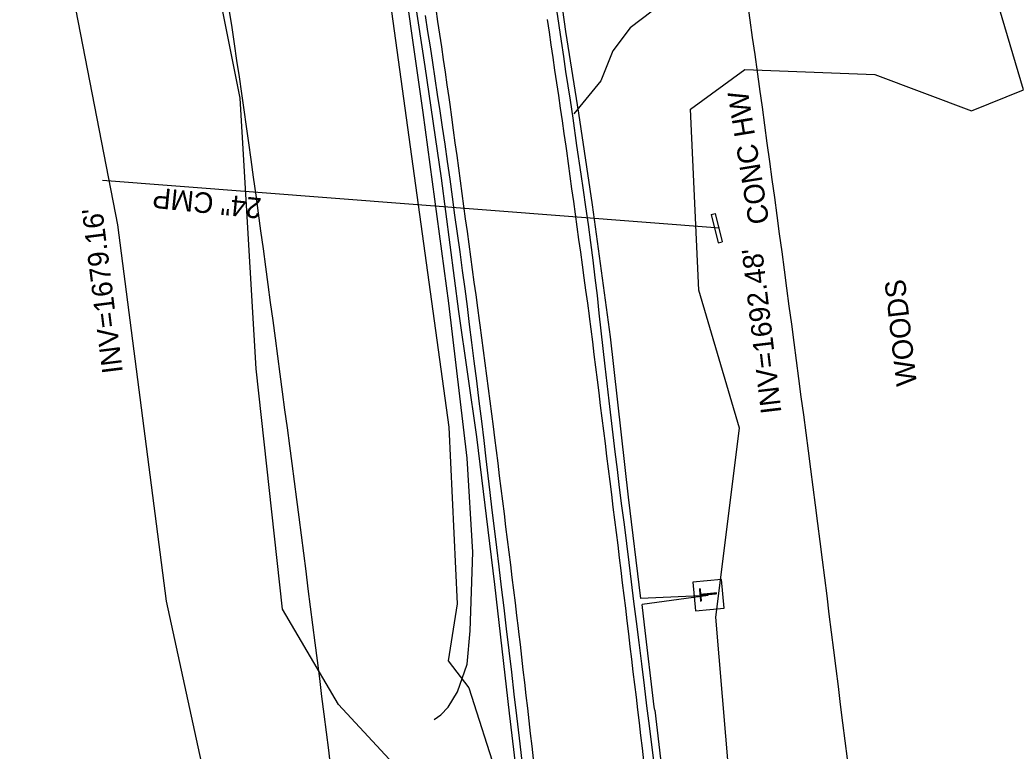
# Model space of a CAD drawing. Extents: x 472260 to 482161, y 489063 to 507124.
# Drawn here: x 477899.5 to 478093.4, y 498501.7 to 498644 of the extents above; entities that cross this region are included whole.
import ezdxf

# ---------------------------------------------------------------- set-up
doc = ezdxf.new("R2010")
doc.units = 0
for name, color, linetype in [('Exist Structure Minor Drop Inlet Cogo Elevation', 7, 'Continuous'), ('Exist Structure Minor Pipes CMP 30 Inch', 7, 'Continuous'), ('Exist Structure Minor Pipes HDPE 18 Inch', 7, 'Continuous'), ('Prop Drainage Structure Catch Basin Convert From Junction Box Label', 7, 'Continuous'), ('Prop Drainage Structure Drop Inlet Grate 2 Narrow Slots and Sag Grates 840 24 CELL', 7, 'Continuous'), ('Prop Drainage Structure Headwall CELL', 7, 'Continuous'), ('Prop Drainage Structure Pipe RCP 18in Class III', 7, 'Continuous'), ('Prop Drainage Structure Pipe RCP 66in Class III', 7, 'Continuous'), ('Prop Drainage Structure Pipe Stub Out CELL', 7, 'Continuous'), ('Prop Drainage Structure Plot Symbol 50 Scale', 7, 'Continuous'), ('Prop Drainage Structure Plot Symbol 50 Scale CELL', 7, 'Continuous'), ('Prop Drainage Structure Tops and Inverts LABEL', 7, 'Continuous'), ('Prop Earthen Structure Head Ditch', 7, 'Continuous'), ('Prop Erosion Rip Rap Class B', 7, 'Continuous'), ('Prop Erosion Rip Rap Pad at Outlet Label', 7, 'Continuous')]:
    doc.layers.add(name, color=color, linetype=linetype)

msp = doc.modelspace()

# ---------------------------------------------------------------- linework, layer by layer
at = {"layer": 'Exist Structure Minor Drop Inlet Cogo Elevation'}
for centre, radius, start, end in [((475642.7, 498298.63), 2423.66, 7.87106, 10.42705), ((475642.7, 498298.63), 2323.66, 7.87106, 10.42705), ((469239.4, 497413.39), 8887.86, 6.405023, 7.871057), ((469239.4, 497413.39), 8787.86, 6.405023, 7.871057)]:
    msp.add_arc(centre, radius, start, end, dxfattribs=at)
at = {"layer": 'Prop Drainage Structure Catch Basin Convert From Junction Box Label'}
for p, q in [((478033.49, 498531.98), (478020.37, 498531.37)), ((478033.49, 498531.98), (478020.58, 498530.25)), ((478023.05, 498509.69), (478022.98, 498510.29))]:
    msp.add_line(p, q, dxfattribs=at)
for points in [[(478020.37, 498531.37), (478017.95, 498551.09), (478014.43, 498582.34), (478010.97, 498607.98), (478008.3, 498625.86), (478005.77, 498641.71), (478003, 498661.43), (477999.51, 498683.4), (477996.51, 498701.33)], [(478002.63, 498442.95), (478002.08, 498447.9), (477997.91, 498482.93), (477994.76, 498509.09), (477991.94, 498534.13), (477988.4, 498562.87), (477984.93, 498587.23), (477981.55, 498613.17), (477978.36, 498634.94), (477973.78, 498665.15), (477969.61, 498690.6), (477968.51, 498697.7)], [(478022.98, 498510.29), (478021.09, 498526.24), (478020.58, 498530.25)], [(478023.05, 498509.69), (478024.96, 498493.54), (478028.85, 498462.94), (478029.49, 498456.54)]]:
    msp.add_lwpolyline(points, dxfattribs=at)
at = {"layer": 'Prop Drainage Structure Drop Inlet Grate 2 Narrow Slots and Sag Grates 840 24 CELL'}
for points in [[(477999.46, 498500.17), (477999.17, 498502.65), (477998.89, 498505.13), (477998.61, 498507.6), (477998.32, 498510.08), (477998.04, 498512.55), (477997.75, 498515.03), (477997.47, 498517.5), (477997.19, 498519.98), (477996.9, 498522.46), (477996.62, 498524.93), (477996.54, 498525.6), (477996.24, 498528.07), (477995.93, 498530.54), (477995.62, 498533.01), (477995.32, 498535.49), (477995.01, 498537.96), (477994.7, 498540.43), (477994.39, 498542.9), (477994.09, 498545.37), (477993.78, 498547.85), (477993.47, 498550.32), (477993.17, 498552.79), (477992.86, 498555.26), (477992.55, 498557.73), (477992.25, 498560.21), (477991.94, 498562.68), (477991.67, 498564.85), (477991.34, 498567.32), (477991.01, 498569.79), (477990.69, 498572.26), (477990.36, 498574.73), (477990.03, 498577.2), (477989.7, 498579.66), (477989.37, 498582.13), (477989.05, 498584.6), (477988.93, 498585.51), (477988.59, 498587.98), (477988.26, 498590.45), (477987.92, 498592.92), (477987.59, 498595.39), (477987.25, 498597.86), (477986.91, 498600.33), (477986.58, 498602.8), (477986.24, 498605.26), (477985.91, 498607.73), (477985.57, 498610.2), (477985.24, 498612.67), (477984.9, 498615.14), (477984.57, 498617.61), (477984.23, 498620.08), (477983.9, 498622.55), (477983.56, 498625.02), (477983.23, 498627.49), (477983.04, 498628.89), (477982.67, 498631.35), (477982.31, 498633.82), (477981.94, 498636.29), (477981.58, 498638.75), (477981.21, 498641.22), (477980.85, 498643.69), (477980.48, 498646.15)], [(478020.96, 498499.8), (478020.67, 498502.28), (478020.37, 498504.75), (478020.07, 498507.22), (478019.78, 498509.7), (478019.48, 498512.17), (478019.18, 498514.65), (478018.89, 498517.12), (478018.59, 498519.6), (478018.29, 498522.07), (478018, 498524.55), (478017.7, 498527.02), (478017.4, 498529.5), (478017.11, 498531.97), (478016.81, 498534.44), (478016.53, 498536.82), (478016.22, 498539.29), (478015.91, 498541.76), (478015.6, 498544.23), (478015.29, 498546.71), (478014.99, 498549.18), (478014.68, 498551.65), (478014.37, 498554.13), (478014.06, 498556.6), (478013.75, 498559.07), (478013.45, 498561.54), (478013.14, 498564.02), (478012.83, 498566.49), (478012.52, 498568.96), (478012.22, 498571.43), (478011.91, 498573.91), (478011.6, 498576.38), (478011.29, 498578.85), (478010.98, 498581.33), (478010.68, 498583.8), (478010.37, 498586.27), (478010.35, 498586.42), (478010.01, 498588.89), (478009.67, 498591.36), (478009.33, 498593.82), (478008.99, 498596.29), (478008.65, 498598.76), (478008.31, 498601.23), (478007.97, 498603.7), (478007.63, 498606.17), (478007.29, 498608.64), (478006.95, 498611.11), (478006.61, 498613.58), (478006.27, 498616.05), (478005.93, 498618.52), (478005.81, 498619.39), (478005.45, 498621.85), (478005.09, 498624.32), (478004.72, 498626.79), (478004.36, 498629.25), (478004, 498631.72), (478003.63, 498634.19), (478003.27, 498636.65), (478002.91, 498639.12), (478002.54, 498641.58), (478002.18, 498644.05)]]:
    msp.add_lwpolyline(points, dxfattribs=at)
at = {"layer": 'Prop Drainage Structure Headwall CELL'}
msp.add_line((477915.57, 498612.76), (478035.68, 498603.54), dxfattribs=at)
at = {"layer": 'Prop Drainage Structure Pipe RCP 18in Class III'}
msp.add_lwpolyline([(478067.38, 498733.66), (478056.64, 498702.95), (478045.19, 498672.47), (478038.91, 498659.85), (478033.38, 498654.47), (478024.69, 498647.29), (478018.26, 498642.42), (478014.87, 498637.95), (478012.54, 498632.09), (478007.31, 498625.71)], dxfattribs=at)
at = {"layer": 'Prop Drainage Structure Pipe Stub Out CELL'}
for points in [[(478022.93, 498499.35), (478022.49, 498502.95), (478022.03, 498506.64), (478021.55, 498510.48), (478021.05, 498514.49), (478020.53, 498518.65), (478020, 498522.83), (478019.5, 498526.89), (478019.01, 498530.83), (478018.55, 498534.64), (478018.09, 498538.38), (478017.62, 498542.09), (478017.16, 498545.77), (478016.68, 498549.42), (478016.22, 498553.01), (478015.78, 498556.51), (478015.35, 498559.91), (478014.96, 498563.23), (478014.57, 498566.52), (478014.19, 498569.84), (478013.8, 498573.21), (478013.42, 498576.61), (478013.04, 498580.04), (478012.66, 498583.46), (478012.27, 498586.89), (478011.89, 498590.33), (478011.48, 498593.77), (478011.06, 498597.22), (478010.62, 498600.69), (478010.15, 498604.17), (478009.67, 498607.58), (478009.21, 498610.85), (478008.75, 498613.96), (478007.9, 498619.53), (478007.16, 498624.85), (478006.64, 498628.37), (478005.78, 498633.92), (478005.33, 498636.88), (478004.88, 498639.87), (478004.42, 498642.9), (478003.97, 498645.93)], [(477997.28, 498499.77), (477996.74, 498504.25), (477996.23, 498508.58), (477995.72, 498512.81), (477995.22, 498517.04), (477994.72, 498521.25), (477994.22, 498525.46), (477993.73, 498529.6), (477993.25, 498533.62), (477992.77, 498537.54), (477992.3, 498541.34), (477991.84, 498545.02), (477991.41, 498548.57), (477991.01, 498551.99), (477990.64, 498555.28), (477990.27, 498558.6), (477989.85, 498562.14), (477989.4, 498565.87), (477988.9, 498569.81), (477988.4, 498573.77), (477987.92, 498577.58), (477987.46, 498581.23), (477987.02, 498584.73), (477986.58, 498588.18), (477986.12, 498591.68), (477985.65, 498595.23), (477985.16, 498598.82), (477984.67, 498602.43), (477984.17, 498605.99), (477983.68, 498609.52), (477983.2, 498613.01), (477982.71, 498616.44), (477982.23, 498619.8), (477981.74, 498623.09), (477981.26, 498626.31), (477980.78, 498629.47), (477980.3, 498632.59), (477979.83, 498635.67), (477979.37, 498638.71), (477978.91, 498641.74), (477978.43, 498644.81)]]:
    msp.add_lwpolyline(points, dxfattribs=at)
at = {"layer": 'Prop Drainage Structure Plot Symbol 50 Scale'}
for p, q in [((478034.03, 498606.1), (478034.84, 498606.3)), ((478034.03, 498606.1), (478035.4, 498600.57)), ((478034.84, 498606.3), (478036.21, 498600.77)), ((478035.4, 498600.57), (478036.21, 498600.77))]:
    msp.add_line(p, q, dxfattribs=at)
at = {"layer": 'Prop Drainage Structure Plot Symbol 50 Scale CELL'}
msp.add_lwpolyline([(477980.13, 498507.83), (477981.43, 498508.73), (477982.83, 498510.24), (477984.67, 498513.24), (477986.54, 498518.59), (477987.15, 498525.08), (477987.62, 498540.38), (477986.53, 498558.71), (477982.99, 498588.89), (477977.95, 498625.97), (477973.03, 498660.6), (477967.5, 498693.64), (477966.35, 498699.59)], dxfattribs=at)
at = {"layer": 'Prop Drainage Structure Tops and Inverts LABEL'}
for points in [[(477963.92, 498311.35), (477977.85, 498311.67), (477991.77, 498320.81), (477996.36, 498327.92), (477987.9, 498370.28), (477978.86, 498428.47), (477975.53, 498495.68), (477961.52, 498510.8), (477950.56, 498529.32), (477945.43, 498576.07), (477942.36, 498628.75), (477934.97, 498665.8), (477920.5, 498695.73), (477916.85, 498708.28)], [(477961.94, 498706.58), (477971.52, 498647.49), (477982.99, 498564.73), (477984.62, 498530.33), (477982.85, 498519.27), (477986.87, 498514.03), (477992.36, 498496.75), (478005.53, 498381.95), (478017.22, 498287.93), (478027.98, 498194.35)]]:
    msp.add_lwpolyline(points, dxfattribs=at)
at = {"layer": 'Prop Erosion Rip Rap Class B'}
msp.add_line((478033.49, 498531.98), (478033.49, 498531.98), dxfattribs=at)
msp.add_lwpolyline([(478036.57, 498529.54), (478036.03, 498535.11), (478030.46, 498534.57), (478031, 498529), (478036.57, 498529.54)], dxfattribs=at)
at = {"layer": 'Prop Erosion Rip Rap Pad at Outlet Label'}
for points in [[(478071.03, 498217.47), (478056.11, 498323.15), (478040.82, 498458.32), (478034.94, 498527.74), (478039.59, 498564.51), (478031.67, 498591.42), (478030.01, 498626.63), (478040.61, 498634.33), (478065.91, 498633.36), (478084.75, 498626.27), (478094.83, 498630.37), (478078.73, 498684.72), (478096.71, 498735.02)], [(477899.46, 498701.89), (477918.46, 498604.12), (477927.94, 498530.85), (477937.69, 498486.12), (477946.46, 498424.92), (477963.92, 498311.35), (477964.48, 498292.29), (477968.75, 498259.54), (477979.45, 498191.25)]]:
    msp.add_lwpolyline(points, dxfattribs=at)

# ---------------------------------------------------------------- texts
at = {"layer": 'Exist Structure Minor Pipes CMP 30 Inch'}
msp.add_text('CONC HW', height=4, rotation=99.2551, dxfattribs=at).set_placement((478045.37, 498604.56))
at = {"layer": 'Exist Structure Minor Pipes HDPE 18 Inch'}
for s, rotation, p in [("INV=1679.16'", 97.1755, (477919.51, 498575.43)), ("INV=1692.48'", 96.7462, (478047.75, 498567.57))]:
    msp.add_text(s, height=4, rotation=rotation, dxfattribs=at).set_placement(p)
at = {"layer": 'Prop Drainage Structure Pipe RCP 66in Class III'}
msp.add_text('WOODS', height=4, rotation=96.515, dxfattribs=at).set_placement((478074.12, 498572.99))
at = {"layer": 'Prop Earthen Structure Head Ditch'}
msp.add_text('24" CMP', height=4, rotation=174.1875, dxfattribs=at).set_placement((477946.63, 498609.26))
at = {"layer": 'Prop Erosion Rip Rap Class B'}
msp.add_text('T', height=3.42, rotation=95.5123, dxfattribs=at).set_placement((478035.31, 498531.02))

doc.saveas('drawing.dxf')
